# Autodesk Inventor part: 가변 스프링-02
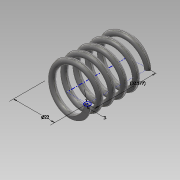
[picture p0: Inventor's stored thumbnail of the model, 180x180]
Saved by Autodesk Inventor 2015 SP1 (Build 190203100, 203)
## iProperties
Created: 2014-12
Part Number: 가변 스프링-02
Material: 강철, 탄소
Document SubType Name: Modeling
Designer: mypark
Density: 7.85 g/cm^3
Appearance: 반연마
Mass: 18.8065 g
Surface Area: 32.5077 cm^2
Volume: 2.39574 cm^3
Author: mypark
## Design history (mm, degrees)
sketch "스케치1"
  geometry: L1 (0, 0)-(11, 0); L2 (11, 0)-(11, 32.577); L3 (11, 32.577)-(0, 32.577); L4 (0, 32.577)-(0, 0); C1 r 1.5 at (11, 0)
  constraints: 8 end point, 2 parallel, 1 centre point, 1 coincident, 1 horizontal, 1 perpendicular
  dimensions: "d0" = 32.5769 distance of L1.end L2.end (derived); "d1" = 3 diameter of C1; "d2" = 22 diameter of C1.centre L4
feature "코일1" sketch "스케치1" pitch "d3" = 10; turns "d5" = 5; dims "d4" = 32.5769 (= d0), "d6" = 0, angle "d7" = 90 deg, angle "d8" = 90 deg, "d9" = 0, "d10" = 0
sketch "스케치2"
  geometry: L1 (-12.5, 0)-(-9.5, 0) reference; 1 further point
  constraints: 1 horizontal alignment
extrude "돌출1" cut sketch "스케치2" stored distance "d11" = 10; taper "d12" = 0 deg
node "작업 평면1"
sketch "스케치3"
  geometry: L1 (3, 0)-(0, 0) reference; 1 further point
  constraints: 1 horizontal alignment
extrude "돌출2" cut sketch "스케치3" stored distance "d13" = 10; taper "d14" = 0 deg
node "솔리드1"
node "절단 모서리 투영1"
node "절단 모서리 투영2"
